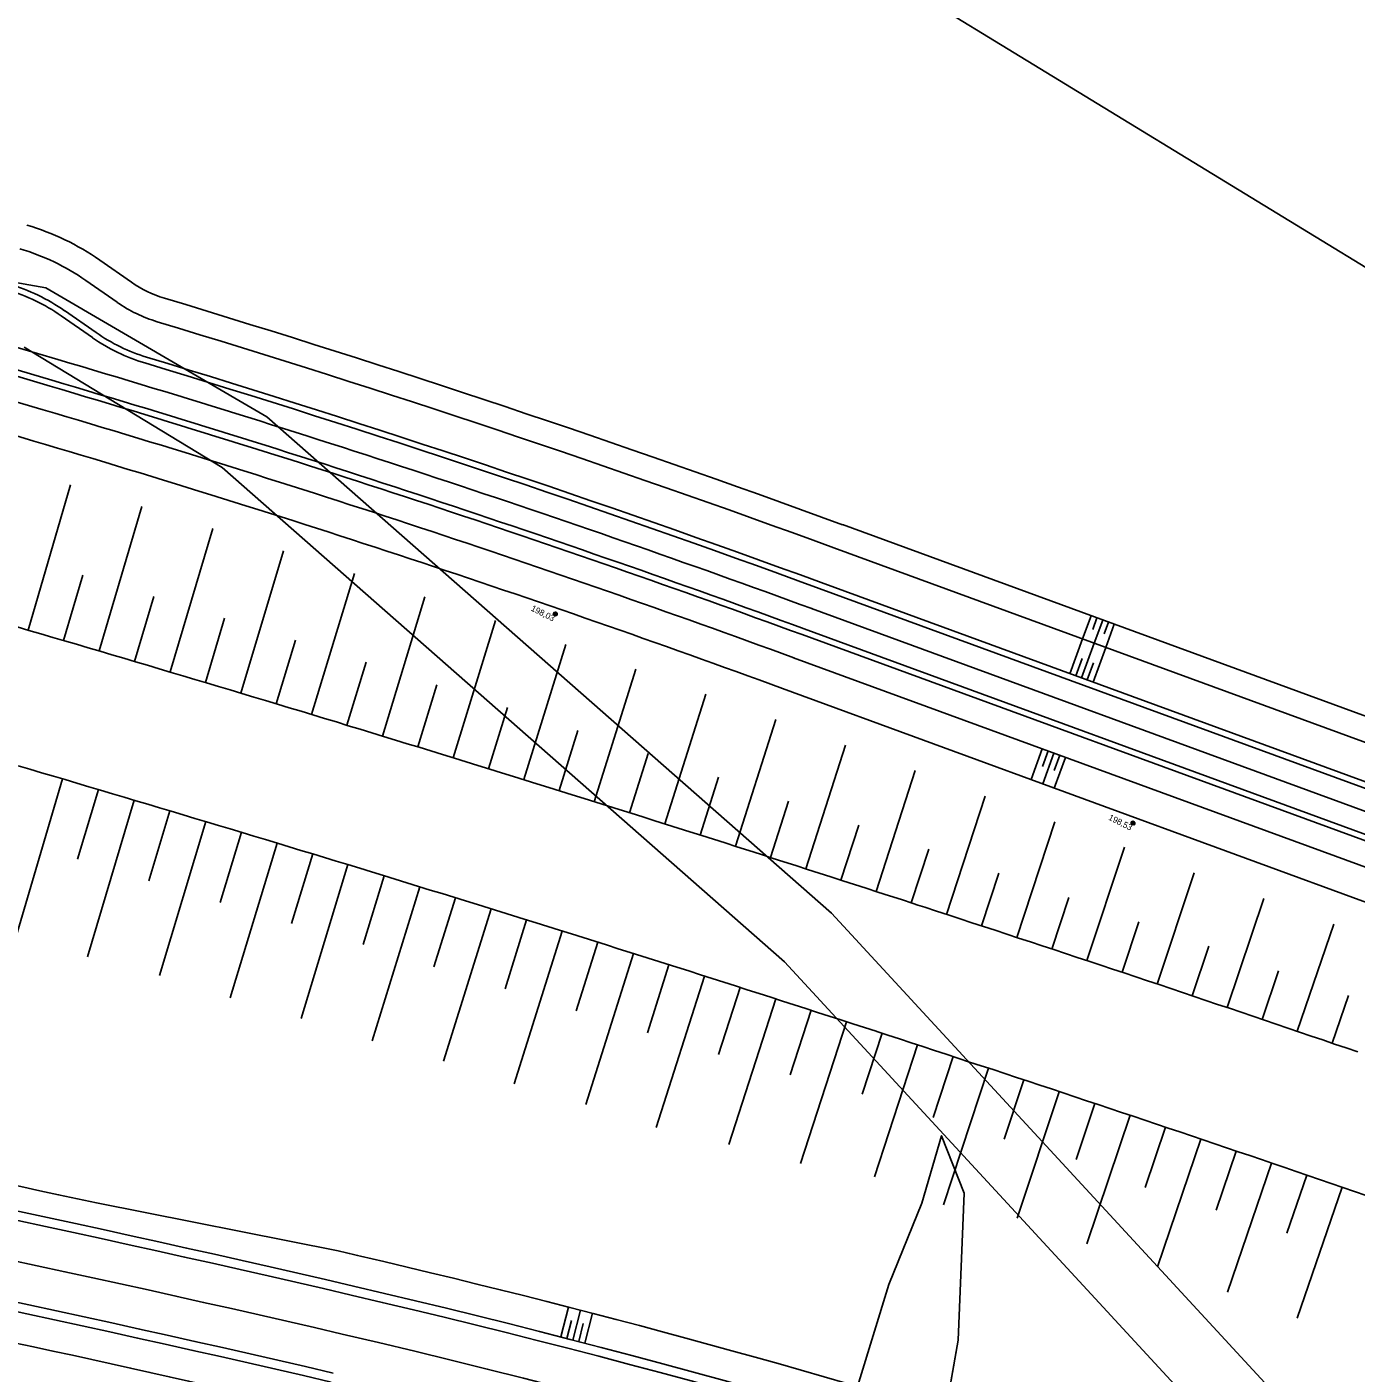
# Model space of a CAD drawing. Extents: x -551750 to -547457, y -1150683 to -1148508.
# Drawn here: x -550912.1 to -550804.2, y -1148814.9 to -1148705.6 of the extents above; entities that cross this region are included whole.
import ezdxf

# ---------------------------------------------------------------- set-up
doc = ezdxf.new("R2010")
doc.units = 0
for name, color, linetype in [('D02_ZaplUzemi20Vody', 7, 'Continuous'), ('D03_ZaplUzemi100Vody', 7, 'Continuous'), ('SO221815_VYSKOPIS', 7, 'Continuous'), ('u_IP17', 7, 'Continuous'), ('u_IP17_srafa', 7, 'Continuous'), ('u_ochranne_pasmo_CD', 7, 'Continuous'), ('u_trat navrh', 7, 'Continuous')]:
    doc.layers.add(name, color=color, linetype=linetype)

# ---------------------------------------------------------------- blocks, each defined once
blk = doc.blocks.new('SO221824_VYSKOPIS')
at = {"layer": 'SO221815_VYSKOPIS'}
for p, q in [((0.12, -0.09), (-0.12, 0.09)), ((0.09, 0.12), (-0.09, -0.12)), ((0.09, 0.12), (0, 0)), ((0, 0), (0.12, -0.09))]:
    blk.add_line(p, q, dxfattribs=at)
blk.add_lwpolyline([(-0.09, -0.12), (0, 0), (-0.12, 0.09)], dxfattribs=at)
blk.add_circle((0, 0), 0.15, dxfattribs=at)
for start, end in [(145.362, 235.1538), (325.362, 55.1538)]:
    blk.add_arc((0, 0), 0.15, start, end, dxfattribs=at)

msp = doc.modelspace()

# ---------------------------------------------------------------- linework, layer by layer
at = {"layer": 'D02_ZaplUzemi20Vody'}
msp.add_lwpolyline([(-550912.3, -1148731.6), (-550896.22, -1148741.39), (-550850.59, -1148781.5), (-550803.72, -1148832.3), (-550780.99, -1148857.84), (-550750.48, -1148893.58), (-550736.72, -1148911.7), (-550729.53, -1148926.8), (-550718.48, -1148952.6), (-550708.97, -1148984.08), (-550705.33, -1149008.81), (-550704.61, -1149029.83), (-550710.53, -1149089.8)], dxfattribs=at)
at = {"layer": 'D03_ZaplUzemi100Vody'}
msp.add_lwpolyline([(-550923.25, -1148724.56), (-550910.54, -1148726.8), (-550892.6, -1148737.27), (-550846.76, -1148777.57), (-550799.66, -1148828.62), (-550776.86, -1148854.24), (-550746.22, -1148890.14), (-550732.01, -1148908.84), (-550724.54, -1148924.55), (-550713.33, -1148950.72), (-550703.61, -1148982.89), (-550699.87, -1149008.32), (-550699.12, -1149030.01), (-550705.1, -1149090.59)], dxfattribs=at)
at = {"layer": 'u_IP17'}
for points in [[(-550837.83, -1148795.62), (-550839.44, -1148801.11), (-550842.12, -1148807.69), (-550845.72, -1148819.42), (-550848.32, -1148831.42), (-550855.99, -1148876.44), (-550864.24, -1148922.29), (-550871.72, -1148953.2), (-550873.29, -1148961.31), (-550876.86, -1148984.92), (-550879.01, -1149003.49), (-550880.48, -1149016.26), (-550880.39, -1149028.48), (-550877.44, -1149050.4), (-550875.79, -1149066.52), (-550875.6, -1149089.61)], [(-550837.83, -1148795.62), (-550836, -1148800.28), (-550836.49, -1148812.22), (-550840.86, -1148837.25), (-550847.41, -1148874.18), (-550854.67, -1148916.87), (-550859.95, -1148946.62), (-550865.43, -1149000.99), (-550867.06, -1149034.41), (-550867.87, -1149048.76), (-550869.33, -1149071.89)]]:
    msp.add_lwpolyline(points, dxfattribs=at)
at = {"layer": 'u_IP17_srafa'}
msp.add_lwpolyline([(-550869.33, -1149071.89), (-550865.43, -1149000.99), (-550859.95, -1148946.62), (-550844.14, -1148855.72), (-550836.49, -1148812.22), (-550836, -1148800.28), (-550837.83, -1148795.62), (-550839.44, -1148801.11), (-550842.12, -1148807.69), (-550845.72, -1148819.42), (-550848.32, -1148831.42), (-550852.16, -1148853.93), (-550855.99, -1148876.44), (-550863.13, -1148916.53), (-550864.24, -1148922.29), (-550867.72, -1148936.4), (-550871.19, -1148950.5), (-550872.24, -1148955.91), (-550876.86, -1148984.92), (-550880.48, -1149016.26), (-550880.39, -1149028.48), (-550877.44, -1149050.4), (-550875.79, -1149066.52), (-550875.41, -1149112.7)], dxfattribs=at)
at = {"layer": 'u_ochranne_pasmo_CD'}
msp.add_lwpolyline([(-551192.01, -1148633.8), (-551157.64, -1148630.18), (-551128.55, -1148628.56), (-551093.1, -1148628.4), (-551065.82, -1148629.19), (-551032.97, -1148632.59), (-551007.77, -1148636.86), (-550975.72, -1148645.44), (-550950.32, -1148653.02), (-550933.85, -1148658.78), (-550881.95, -1148680.12), (-550842.85, -1148701.03), (-550797.65, -1148728.66), (-550648.81, -1148835.14), (-550577.65, -1148890.43), (-550478.43, -1148960.24), (-550334.99, -1149075.5), (-550242.86, -1149142.59), (-550154.88, -1149215.07), (-550068.29, -1149277.57)], dxfattribs=at)
at = {"layer": 'u_trat navrh'}
for p, q in [((-550981.97, -1148711.25), (-550909.55, -1148732.61)), ((-550982.6, -1148713.4), (-550910.19, -1148734.77)), ((-550982.46, -1148712.92), (-550910.05, -1148734.29)), ((-550983.17, -1148715.32), (-550910.76, -1148736.69)), ((-550903.59, -1148726.33), (-550906.15, -1148724.55)), ((-550904.74, -1148727.97), (-550907.29, -1148726.19)), ((-550906.74, -1148730.84), (-550909.29, -1148729.06)), ((-550906.45, -1148730.43), (-550909.01, -1148728.65)), ((-550914.44, -1148738.36), (-550911.51, -1148739.23)), ((-550911.97, -1148754.58), (-550908.52, -1148742.79)), ((-550906.21, -1148756.27), (-550902.74, -1148744.54)), ((-550900.45, -1148757.98), (-550896.98, -1148746.32)), ((-550730.77, -1148788.22), (-550845.88, -1148746.02)), ((-550894.7, -1148759.7), (-550891.23, -1148748.14)), ((-550731.56, -1148790.07), (-550846.57, -1148747.9)), ((-550909.09, -1148755.43), (-550907.53, -1148750.13)), ((-550888.96, -1148761.43), (-550885.49, -1148749.99)), ((-550730, -1148793.83), (-550847.6, -1148750.72)), ((-550903.33, -1148757.13), (-550901.77, -1148751.86)), ((-550883.22, -1148763.18), (-550879.76, -1148751.88)), ((-550730.17, -1148794.3), (-550847.77, -1148751.19)), ((-550730.77, -1148795.94), (-550848.38, -1148752.83)), ((-550897.58, -1148758.84), (-550896.02, -1148753.61)), ((-550877.48, -1148764.94), (-550874.05, -1148753.8)), ((-550826.39, -1148755.3), (-550825.7, -1148753.42)), ((-550825.57, -1148754.53), (-550825.23, -1148753.59)), ((-550825.45, -1148755.64), (-550824.76, -1148753.77)), ((-550824.64, -1148754.88), (-550824.29, -1148753.94)), ((-550824.51, -1148755.99), (-550823.82, -1148754.11)), ((-550743.53, -1148793.66), (-550849.15, -1148754.94)), ((-550731.38, -1148797.59), (-550848.98, -1148754.47)), ((-550827.42, -1148758.12), (-550826.39, -1148755.3)), ((-550891.83, -1148760.57), (-550890.27, -1148755.39)), ((-550871.75, -1148766.72), (-550868.34, -1148755.76)), ((-550826.48, -1148758.46), (-550825.45, -1148755.64)), ((-550825.54, -1148758.81), (-550824.51, -1148755.99)), ((-550886.09, -1148762.31), (-550884.53, -1148757.19)), ((-550744.31, -1148795.51), (-550849.84, -1148756.82)), ((-550826.95, -1148758.29), (-550826.43, -1148756.88)), ((-550826.01, -1148758.63), (-550825.5, -1148757.23)), ((-550866.02, -1148768.51), (-550862.65, -1148757.75)), ((-550880.35, -1148764.06), (-550878.8, -1148759.01)), ((-550795.36, -1148779.62), (-550850.75, -1148759.31)), ((-550860.29, -1148770.31), (-550856.96, -1148759.78)), ((-550874.61, -1148765.83), (-550873.07, -1148760.85)), ((-550854.57, -1148772.12), (-550851.29, -1148761.84)), ((-550868.88, -1148767.61), (-550867.36, -1148762.72)), ((-550848.86, -1148773.95), (-550845.63, -1148763.91)), ((-550863.15, -1148769.41), (-550861.65, -1148764.61)), ((-550829.66, -1148764.22), (-550830.57, -1148766.71)), ((-550829.19, -1148764.39), (-550829.64, -1148765.64)), ((-550828.72, -1148764.56), (-550829.63, -1148767.05)), ((-550828.25, -1148764.74), (-550828.71, -1148765.98)), ((-550827.78, -1148764.91), (-550828.69, -1148767.4)), ((-550843.15, -1148775.8), (-550839.97, -1148765.99)), ((-550909.17, -1148766.66), (-550912.97, -1148779.54)), ((-550857.43, -1148771.22), (-550855.95, -1148766.53)), ((-550906.27, -1148767.52), (-550907.95, -1148773.18)), ((-550903.37, -1148768.38), (-550907.15, -1148781.09)), ((-550851.71, -1148773.04), (-550850.25, -1148768.46)), ((-550837.44, -1148777.66), (-550834.31, -1148768.06)), ((-550900.46, -1148769.25), (-550902.16, -1148774.93)), ((-550897.56, -1148770.12), (-550901.32, -1148782.61)), ((-550846, -1148774.87), (-550844.56, -1148770.41)), ((-550831.74, -1148779.53), (-550828.65, -1148770.14)), ((-550894.66, -1148770.99), (-550896.38, -1148776.68)), ((-550891.77, -1148771.87), (-550895.57, -1148784.44)), ((-550888.87, -1148772.75), (-550890.59, -1148778.4)), ((-550840.29, -1148776.72), (-550838.87, -1148772.36)), ((-550826.04, -1148781.41), (-550822.99, -1148772.21)), ((-550886.01, -1148773.62), (-550889.82, -1148786.11)), ((-550883.08, -1148774.52), (-550884.79, -1148780.09)), ((-550834.59, -1148778.59), (-550833.19, -1148774.32)), ((-550820.34, -1148783.31), (-550817.33, -1148774.29)), ((-550880.18, -1148775.41), (-550884.04, -1148787.91)), ((-550877.29, -1148776.31), (-550879.03, -1148781.91)), ((-550874.4, -1148777.2), (-550878.25, -1148789.58)), ((-550828.89, -1148780.47), (-550827.5, -1148776.29)), ((-550814.66, -1148785.22), (-550811.67, -1148776.36)), ((-550871.51, -1148778.1), (-550873.25, -1148783.69)), ((-550823.19, -1148782.36), (-550821.83, -1148778.26)), ((-550868.62, -1148779.01), (-550872.51, -1148791.42)), ((-550808.97, -1148787.14), (-550806.01, -1148778.44)), ((-550865.73, -1148779.92), (-550867.49, -1148785.49)), ((-550817.5, -1148784.26), (-550816.15, -1148780.24)), ((-550862.84, -1148780.83), (-550866.72, -1148793.08)), ((-550859.96, -1148781.75), (-550861.71, -1148787.27)), ((-550857.07, -1148782.66), (-550860.99, -1148794.96)), ((-550811.81, -1148786.18), (-550810.48, -1148782.23)), ((-550854.19, -1148783.59), (-550855.93, -1148789.04)), ((-550851.3, -1148784.51), (-550855.11, -1148796.34)), ((-550806.13, -1148788.11), (-550804.8, -1148784.23)), ((-550848.42, -1148785.44), (-550850.12, -1148790.69)), ((-550845.54, -1148786.38), (-550849.28, -1148797.89)), ((-550842.66, -1148787.31), (-550844.27, -1148792.25)), ((-550839.78, -1148788.25), (-550843.28, -1148798.95)), ((-550836.9, -1148789.2), (-550838.53, -1148794.15)), ((-550834.03, -1148790.14), (-550837.68, -1148801.23)), ((-550831.15, -1148791.09), (-550832.75, -1148795.9)), ((-550828.28, -1148792.05), (-550831.7, -1148802.32)), ((-550825.41, -1148793), (-550826.92, -1148797.55)), ((-550822.53, -1148793.96), (-550826.04, -1148804.41)), ((-550819.66, -1148794.93), (-550821.31, -1148799.83)), ((-550816.79, -1148795.9), (-550820.3, -1148806.27)), ((-550813.93, -1148796.87), (-550815.56, -1148801.68)), ((-550811.06, -1148797.84), (-550814.63, -1148808.33)), ((-550808.19, -1148798.82), (-550809.81, -1148803.53)), ((-550805.33, -1148799.8), (-550808.98, -1148810.44)), ((-550886.81, -1148804.98), (-550906.43, -1148801.08)), ((-550868.73, -1148811.96), (-550868.11, -1148809.54)), ((-550867.77, -1148812.21), (-550867.14, -1148809.79)), ((-550868.25, -1148812.08), (-550867.88, -1148810.63)), ((-550867.28, -1148812.33), (-550866.91, -1148810.88)), ((-550866.8, -1148812.46), (-550866.17, -1148810.04)), ((-550888.55, -1148811.25), (-550888.55, -1148811.25))]:
    msp.add_line(p, q, dxfattribs=at)
for points in [[(-550912.86, -1148754.32), (-550911.9, -1148754.6), (-550910.93, -1148754.88), (-550909.97, -1148755.17), (-550909.01, -1148755.45), (-550908.05, -1148755.73), (-550907.09, -1148756.01), (-550906.13, -1148756.3), (-550905.17, -1148756.58), (-550904.21, -1148756.86), (-550903.25, -1148757.15), (-550902.29, -1148757.43), (-550901.33, -1148757.72), (-550900.37, -1148758.01), (-550899.41, -1148758.29), (-550898.45, -1148758.58), (-550897.49, -1148758.86), (-550896.53, -1148759.15), (-550895.57, -1148759.44), (-550894.62, -1148759.73), (-550893.66, -1148760.02), (-550892.7, -1148760.3), (-550891.74, -1148760.59), (-550890.78, -1148760.88), (-550889.82, -1148761.17), (-550888.86, -1148761.46), (-550887.91, -1148761.75), (-550886.95, -1148762.04), (-550885.99, -1148762.34), (-550885.03, -1148762.63), (-550884.07, -1148762.92), (-550883.12, -1148763.21), (-550882.16, -1148763.51), (-550881.2, -1148763.8), (-550880.24, -1148764.09), (-550879.29, -1148764.39), (-550878.33, -1148764.68), (-550877.37, -1148764.98), (-550876.42, -1148765.27), (-550875.46, -1148765.57), (-550874.5, -1148765.86), (-550873.55, -1148766.16), (-550872.59, -1148766.46), (-550871.63, -1148766.75), (-550870.68, -1148767.05), (-550869.72, -1148767.35), (-550868.76, -1148767.65), (-550867.81, -1148767.95), (-550866.85, -1148768.24), (-550865.9, -1148768.54), (-550864.94, -1148768.84), (-550863.99, -1148769.14), (-550863.03, -1148769.44), (-550862.08, -1148769.75), (-550861.12, -1148770.05), (-550860.17, -1148770.35), (-550859.21, -1148770.65), (-550858.26, -1148770.95), (-550857.3, -1148771.26), (-550856.35, -1148771.56), (-550855.39, -1148771.86), (-550854.44, -1148772.17), (-550853.49, -1148772.47), (-550852.53, -1148772.78), (-550851.58, -1148773.08), (-550850.63, -1148773.39), (-550849.67, -1148773.69), (-550848.72, -1148774), (-550847.77, -1148774.31), (-550846.81, -1148774.61), (-550845.86, -1148774.92), (-550844.91, -1148775.23), (-550843.95, -1148775.54), (-550843, -1148775.84), (-550842.05, -1148776.15), (-550841.1, -1148776.46), (-550840.14, -1148776.77), (-550839.75, -1148776.9), (-550839.19, -1148777.08), (-550838.24, -1148777.39), (-550837.29, -1148777.7), (-550836.34, -1148778.02), (-550835.38, -1148778.33), (-550834.43, -1148778.64), (-550833.48, -1148778.95), (-550832.53, -1148779.26), (-550831.58, -1148779.58), (-550830.63, -1148779.89), (-550829.68, -1148780.2), (-550828.73, -1148780.52), (-550827.78, -1148780.83), (-550826.83, -1148781.15), (-550825.88, -1148781.46), (-550824.92, -1148781.78), (-550823.97, -1148782.1), (-550823.02, -1148782.41), (-550822.07, -1148782.73), (-550821.13, -1148783.05), (-550820.18, -1148783.36), (-550819.23, -1148783.68), (-550818.28, -1148784), (-550817.33, -1148784.32), (-550816.38, -1148784.64), (-550815.43, -1148784.96), (-550814.48, -1148785.28), (-550813.53, -1148785.6), (-550812.58, -1148785.92), (-550811.63, -1148786.24), (-550810.69, -1148786.56), (-550809.74, -1148786.88), (-550808.79, -1148787.21), (-550807.84, -1148787.53), (-550806.89, -1148787.85), (-550805.95, -1148788.18), (-550805, -1148788.5), (-550804.05, -1148788.82)], [(-550912.79, -1148765.59), (-550911.84, -1148765.87), (-550910.88, -1148766.16), (-550909.92, -1148766.44), (-550908.96, -1148766.72), (-550908.01, -1148767), (-550907.05, -1148767.29), (-550906.09, -1148767.57), (-550905.13, -1148767.86), (-550904.18, -1148768.14), (-550903.22, -1148768.43), (-550902.26, -1148768.71), (-550901.3, -1148769), (-550900.35, -1148769.28), (-550899.39, -1148769.57), (-550898.43, -1148769.86), (-550897.48, -1148770.14), (-550896.52, -1148770.43), (-550895.56, -1148770.72), (-550894.61, -1148771.01), (-550893.65, -1148771.3), (-550892.7, -1148771.59), (-550891.74, -1148771.88), (-550890.78, -1148772.17), (-550889.83, -1148772.46), (-550888.87, -1148772.75), (-550887.92, -1148773.04), (-550886.96, -1148773.33), (-550886.01, -1148773.62), (-550885.05, -1148773.91), (-550884.1, -1148774.21), (-550883.14, -1148774.5), (-550882.19, -1148774.79), (-550881.23, -1148775.09), (-550880.28, -1148775.38), (-550879.33, -1148775.68), (-550878.37, -1148775.97), (-550877.42, -1148776.27), (-550876.46, -1148776.56), (-550875.51, -1148776.86), (-550874.56, -1148777.15), (-550873.6, -1148777.45), (-550872.65, -1148777.75), (-550871.7, -1148778.05), (-550870.74, -1148778.34), (-550869.79, -1148778.64), (-550868.84, -1148778.94), (-550867.88, -1148779.24), (-550866.93, -1148779.54), (-550865.98, -1148779.84), (-550865.03, -1148780.14), (-550864.07, -1148780.44), (-550863.12, -1148780.74), (-550862.17, -1148781.04), (-550861.22, -1148781.34), (-550860.26, -1148781.65), (-550859.31, -1148781.95), (-550858.36, -1148782.25), (-550857.41, -1148782.56), (-550856.46, -1148782.86), (-550855.51, -1148783.16), (-550854.56, -1148783.47), (-550853.6, -1148783.77), (-550852.65, -1148784.08), (-550851.7, -1148784.38), (-550850.75, -1148784.69), (-550849.8, -1148785), (-550848.85, -1148785.3), (-550847.9, -1148785.61), (-550846.95, -1148785.92), (-550846, -1148786.23), (-550845.05, -1148786.53), (-550844.1, -1148786.84), (-550843.15, -1148787.15), (-550843.08, -1148787.17), (-550842.2, -1148787.46), (-550841.25, -1148787.77), (-550840.3, -1148788.08), (-550839.35, -1148788.39), (-550838.4, -1148788.7), (-550837.46, -1148789.01), (-550836.51, -1148789.33), (-550835.56, -1148789.64), (-550834.61, -1148789.95), (-550833.66, -1148790.26), (-550832.71, -1148790.58), (-550831.76, -1148790.89), (-550830.82, -1148791.2), (-550829.87, -1148791.52), (-550828.92, -1148791.83), (-550827.97, -1148792.15), (-550827.03, -1148792.46), (-550826.08, -1148792.78), (-550825.13, -1148793.1), (-550824.18, -1148793.41), (-550823.24, -1148793.73), (-550822.29, -1148794.05), (-550821.34, -1148794.36), (-550820.4, -1148794.68), (-550819.45, -1148795), (-550818.5, -1148795.32), (-550817.56, -1148795.64), (-550816.61, -1148795.96), (-550815.66, -1148796.28), (-550814.72, -1148796.6), (-550813.77, -1148796.92), (-550812.83, -1148797.24), (-550811.88, -1148797.56), (-550810.94, -1148797.88), (-550809.99, -1148798.21), (-550809.05, -1148798.53), (-550808.1, -1148798.85), (-550807.16, -1148799.18), (-550806.21, -1148799.5), (-550805.27, -1148799.82), (-550804.32, -1148800.15), (-550803.38, -1148800.47)]]:
    msp.add_lwpolyline(points, dxfattribs=at)
for centre, radius, start, end in [((-550917.87, -1148741.37), 20.5, 55.1241, 73.559), ((-550917.87, -1148741.37), 18.5, 55.1241, 73.559), ((-550917.87, -1148741.37), 15.5, 55.1241, 73.559), ((-550898.16, -1148718.54), 9.5, 235.1241, 253.1678), ((-550917.87, -1148741.37), 15, 55.1241, 73.559), ((-550898.16, -1148718.54), 11.5, 235.1241, 253.1678), ((-551192.58, -1149691.73), 1007.25, 69.86671, 73.16776), ((-551192.58, -1149691.73), 1005.25, 69.86671, 73.16776), ((-550898.16, -1148718.54), 15, 235.1241, 253.1678), ((-550898.16, -1148718.54), 14.5, 235.1241, 253.1678), ((-551192.58, -1149691.73), 1000, 69.86671, 73.55904), ((-551192.58, -1149691.73), 1001.75, 69.86671, 73.16776), ((-551192.58, -1149691.73), 1002.25, 69.86671, 73.16776), ((-551192.58, -1149691.73), 998.25, 69.86671, 73.55904), ((-551192.58, -1149691.73), 997.75, 69.86671, 73.55904), ((-551192.58, -1149691.73), 995.75, 69.86671, 73.55904), ((-551192.58, -1149691.73), 993.1, 69.86671, 73.55904), ((-551226.7, -1150272.63), 1504, 76.89047, 82.52854), ((-551226.7, -1150272.63), 1503.25, 76.89047, 82.52854), ((-551226.7, -1150272.63), 1506, 77.72157, 81.54129), ((-551226.7, -1150272.63), 1500, 76.89047, 82.52854), ((-551226.7, -1150272.63), 1496.75, 76.89047, 82.52854), ((-551226.7, -1150272.63), 1496, 76.89047, 82.52854), ((-551226.7, -1150272.63), 1506.5, 76.89047, 76.96092), ((-551056.59, -1149542.18), 756.5, 67.46341, 76.89047), ((-551226.7, -1150272.63), 1493.5, 76.89047, 78.86749), ((-551056.59, -1149542.18), 753.25, 51.79075, 76.89047), ((-551056.59, -1149542.18), 754, 51.79075, 76.89047), ((-551056.59, -1149542.18), 750, 47.42068, 76.89047)]:
    msp.add_arc(centre, radius, start, end, dxfattribs=at)

# ---------------------------------------------------------------- block references
at = {"layer": 'u_trat navrh', "rotation": -31.851985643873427}
for p in [(-550869.18, -1148753.27), (-550822.3, -1148770.25)]:
    msp.add_blockref('SO221824_VYSKOPIS', p, dxfattribs=at)

# ---------------------------------------------------------------- texts
at = {"layer": 'u_trat navrh'}
for s, p in [('198,03', (-550871.21, -1148752.97)), ('198,53', (-550824.34, -1148769.95))]:
    msp.add_text(s, height=0.5, rotation=333.2568, dxfattribs=at).set_placement(p)

doc.saveas('drawing.dxf')
